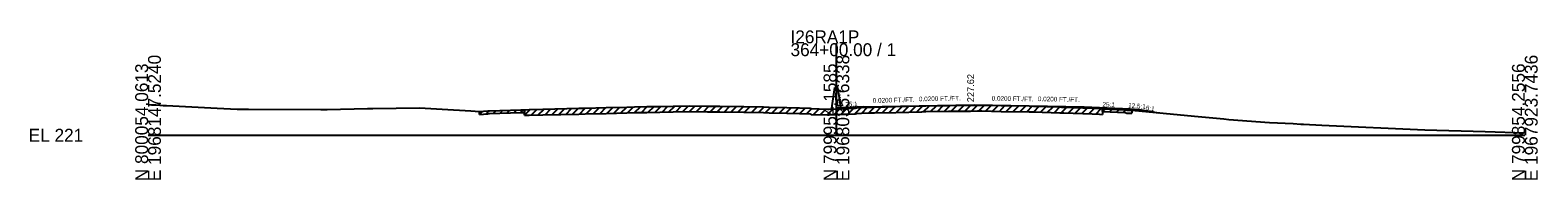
# Model space of a CAD drawing. Extents: x -26 to 304, y -10 to 7527.
# Drawn here: x -25.7 to 302.8, y 6990.3 to 7022.8 of the extents above; entities that cross this region are included whole.
import ezdxf

# ---------------------------------------------------------------- set-up
doc = ezdxf.new("R2010")
doc.units = 0
for name, color, linetype in [('RD_GPK_XS_Cell', 7, 'Continuous'), ('RD_XS_Base', 7, 'Continuous'), ('RD_XS_Box', 7, 'Continuous'), ('RD_XS_EarthShd', 7, 'Continuous'), ('RD_XS_ExGround', 7, 'Continuous'), ('RD_XS_ExPaveRet', 7, 'Continuous'), ('RD_XS_Misc_Line', 7, 'Continuous'), ('RD_XS_Pave', 7, 'Continuous'), ('RD_XS_PaveShd', 7, 'Continuous'), ('RD_XS_TX_Elev_EX', 7, 'Continuous'), ('RD_XS_TX_Elev_PR', 7, 'Continuous'), ('RD_XS_TX_Misc', 7, 'Continuous'), ('RD_XS_TX_MkPT', 7, 'Continuous'), ('RD_XS_TX_Profile', 7, 'Continuous'), ('RD_XS_TX_Station', 7, 'Continuous')]:
    doc.layers.add(name, color=color, linetype=linetype)

msp = doc.modelspace()

# ---------------------------------------------------------------- linework, layer by layer
at = {"layer": 'RD_GPK_XS_Cell'}
for p, q in [((150, 7000), (150, 7020)), ((0, 7000), (150, 7000)), ((150, 7000), (300, 7000))]:
    msp.add_line(p, q, dxfattribs=at)
at = {"layer": 'RD_XS_Base'}
for p, q in [((150, 7005.75), (150, 7005.9)), ((214, 7005.42), (214, 7005.74))]:
    msp.add_line(p, q, dxfattribs=at)
at = {"layer": 'RD_XS_Box'}
msp.add_line((216, 7005.58), (220.21, 7004.88), dxfattribs=at)
at = {"layer": 'RD_XS_EarthShd'}
for p, q in [((149, 7005.92), (149.67, 7010.4)), ((150, 7010.4), (149.67, 7010.4)), ((150, 7010.4), (150.33, 7010.4)), ((151, 7005.92), (150.33, 7010.4)), ((214, 7005.74), (216, 7005.58))]:
    msp.add_line(p, q, dxfattribs=at)
at = {"layer": 'RD_XS_ExGround'}
msp.add_lwpolyline([(0, 7006.67), (0.75, 7006.63), (1.7, 7006.58), (2.53, 7006.54), (3.28, 7006.49), (4.01, 7006.45), (15.09, 7005.87), (19.41, 7005.7), (21.91, 7005.67), (37.63, 7005.59), (39, 7005.57), (47.84, 7005.81), (48.6, 7005.82), (49.01, 7005.83), (59.15, 7005.95), (64.09, 7005.68), (70.33, 7005.3), (72.19, 7005.13), (73.1, 7005.2), (74.06, 7005.27), (74.37, 7005.34), (81.26, 7005.55), (83.06, 7005.61), (86, 7005.68), (93.88, 7005.86), (95.27, 7005.89), (99.82, 7006), (104.36, 7006.13), (105.98, 7006.17), (108.66, 7006.22), (111.54, 7006.28), (114.44, 7006.34), (118.09, 7006.41), (121.91, 7006.35), (123.48, 7006.32), (124.6, 7006.31), (129.85, 7006.26), (134.14, 7006.16), (135.35, 7006.13), (139.19, 7006.04), (141.98, 7005.98), (144.26, 7005.87), (144.51, 7005.79), (148.03, 7005.68), (148.4, 7005.67), (150, 7005.75), (151.08, 7005.81), (152.19, 7005.84), (154.16, 7005.89), (154.41, 7005.98), (155.47, 7006.02), (157.37, 7006.09), (158.31, 7006.11), (162.97, 7006.22), (168.6, 7006.37), (168.93, 7006.38), (169.46, 7006.39), (174.39, 7006.46), (179.24, 7006.51), (180.71, 7006.53), (181.65, 7006.52), (185.92, 7006.44), (192, 7006.37), (192.97, 7006.35), (198.68, 7006.14), (199.05, 7006.13), (199.52, 7006.11), (205.76, 7005.9), (207.3, 7005.82), (212.95, 7005.55), (213.31, 7005.43), (214.4, 7005.42), (228.05, 7004.15), (234.4, 7003.54), (235.53, 7003.43), (244.33, 7002.78), (249.51, 7002.52), (251.18, 7002.44), (251.79, 7002.39), (255.78, 7002.21), (278.21, 7001.17), (291.37, 7000.82), (300, 7000.51)], dxfattribs=at)
at = {"layer": 'RD_XS_ExPaveRet'}
for p, q in [((72.19, 7004.51), (72.19, 7005.13)), ((72.19, 7004.51), (73.1, 7004.57)), ((73.1, 7004.57), (74.06, 7004.64)), ((74.06, 7004.64), (74.37, 7004.72)), ((74.37, 7004.72), (81.26, 7004.93)), ((81.26, 7004.93), (82, 7004.95)), ((82, 7004.33), (82, 7005.58)), ((82, 7005.58), (82, 7004.95)), ((82, 7004.33), (83.06, 7004.36)), ((83.06, 7004.36), (86, 7004.43)), ((86, 7004.43), (93.88, 7004.61)), ((93.88, 7004.61), (95.27, 7004.64)), ((95.27, 7004.64), (99.82, 7004.75)), ((99.82, 7004.75), (104.36, 7004.88)), ((104.36, 7004.88), (105.98, 7004.92)), ((105.98, 7004.92), (108.66, 7004.97)), ((108.66, 7004.97), (111.54, 7005.03)), ((111.54, 7005.03), (114.44, 7005.09)), ((114.44, 7005.09), (118.09, 7005.16)), ((118.09, 7005.16), (121.91, 7005.1)), ((121.91, 7005.1), (123.48, 7005.07)), ((123.48, 7005.07), (124.6, 7005.06)), ((124.6, 7005.06), (129.85, 7005.01)), ((129.85, 7005.01), (134.14, 7004.91)), ((134.14, 7004.91), (135.35, 7004.88)), ((135.35, 7004.88), (139.19, 7004.79)), ((139.19, 7004.79), (141.98, 7004.73)), ((141.98, 7004.73), (144.26, 7004.62)), ((144.26, 7004.62), (144.51, 7004.54)), ((144.51, 7004.54), (148.03, 7004.43)), ((148.03, 7004.43), (148.4, 7004.42)), ((148.4, 7004.42), (150, 7004.5)), ((150, 7004.5), (151.08, 7004.56)), ((151.08, 7004.56), (152.19, 7004.59)), ((152.19, 7004.59), (154.16, 7004.64)), ((154.16, 7004.64), (154.41, 7004.73)), ((154.41, 7004.73), (155.47, 7004.77)), ((155.47, 7004.77), (157.37, 7004.84)), ((157.37, 7004.84), (158.31, 7004.86)), ((158.31, 7004.86), (162.97, 7004.97)), ((162.97, 7004.97), (168.6, 7005.12)), ((168.6, 7005.12), (168.93, 7005.13)), ((168.93, 7005.13), (169.46, 7005.14)), ((169.46, 7005.14), (174.39, 7005.21)), ((174.39, 7005.21), (179.24, 7005.26)), ((179.24, 7005.26), (180.71, 7005.28)), ((180.71, 7005.28), (181.65, 7005.27)), ((181.65, 7005.27), (185.92, 7005.19)), ((185.92, 7005.19), (192, 7005.12)), ((192, 7005.12), (192.97, 7005.1)), ((192.97, 7005.1), (198.68, 7004.89)), ((198.68, 7004.89), (199.05, 7004.88)), ((199.05, 7004.88), (199.52, 7004.86)), ((199.52, 7004.86), (205.76, 7004.65)), ((205.76, 7004.65), (207.3, 7004.57)), ((207.3, 7004.57), (208, 7004.54)), ((208, 7005.79), (208, 7004.54)), ((208, 7005.16), (208, 7005.79)), ((208, 7005.16), (212.95, 7004.93)), ((212.95, 7004.93), (213.31, 7004.81)), ((213.31, 7004.81), (214.4, 7004.79)), ((214.4, 7005.42), (214.4, 7004.79))]:
    msp.add_line(p, q, dxfattribs=at)
at = {"layer": 'RD_XS_Misc_Line'}
for p, q in [((72.19, 7004.51), (72.86, 7005.18)), ((73.69, 7004.62), (74.42, 7005.35)), ((75.19, 7004.74), (75.84, 7005.39)), ((76.69, 7004.79), (77.34, 7005.43)), ((78.19, 7004.83), (78.84, 7005.48)), ((79.69, 7004.88), (80.34, 7005.52)), ((81.19, 7004.93), (81.84, 7005.57)), ((82, 7004.33), (83.29, 7005.61)), ((83.5, 7004.37), (84.78, 7005.65)), ((85, 7004.4), (86.28, 7005.68)), ((86.5, 7004.44), (87.78, 7005.72)), ((88, 7004.47), (89.28, 7005.75)), ((89.5, 7004.51), (90.78, 7005.79)), ((91, 7004.54), (92.28, 7005.82)), ((92.5, 7004.58), (93.78, 7005.85)), ((94, 7004.61), (95.28, 7005.89)), ((95.5, 7004.65), (96.78, 7005.93)), ((97, 7004.68), (98.28, 7005.97)), ((98.5, 7004.72), (99.78, 7006)), ((100, 7004.76), (101.29, 7006.04)), ((101.5, 7004.8), (102.79, 7006.08)), ((103, 7004.84), (104.29, 7006.12)), ((104.5, 7004.88), (105.79, 7006.17)), ((106, 7004.92), (107.27, 7006.2)), ((107.5, 7004.95), (108.77, 7006.23)), ((109, 7004.98), (110.28, 7006.26)), ((110.5, 7005.01), (111.78, 7006.29)), ((112, 7005.04), (113.28, 7006.32)), ((113.5, 7005.07), (114.77, 7006.35)), ((115, 7005.1), (116.27, 7006.37)), ((116.5, 7005.13), (117.77, 7006.4)), ((118, 7005.15), (119.23, 7006.39)), ((119.5, 7005.13), (120.73, 7006.37)), ((121, 7005.11), (122.23, 7006.34)), ((122.5, 7005.09), (123.73, 7006.32)), ((124, 7005.06), (125.24, 7006.3)), ((125.5, 7005.05), (126.74, 7006.29)), ((127, 7005.04), (128.24, 7006.27)), ((128.5, 7005.02), (129.74, 7006.26)), ((130, 7005), (131.22, 7006.23)), ((131.5, 7004.97), (132.72, 7006.19)), ((133, 7004.93), (134.22, 7006.15)), ((134.5, 7004.9), (135.72, 7006.12)), ((136, 7004.86), (137.22, 7006.09)), ((137.5, 7004.83), (138.72, 7006.05)), ((139, 7004.79), (140.22, 7006.02)), ((140.5, 7004.76), (141.72, 7005.98)), ((142, 7004.73), (143.19, 7005.92)), ((143.5, 7004.65), (144.63, 7005.79)), ((145, 7004.52), (146.21, 7005.74)), ((146.5, 7004.48), (147.71, 7005.69)), ((148, 7004.43), (149.28, 7005.72)), ((149.5, 7004.48), (150.82, 7005.79)), ((151, 7004.55), (152.29, 7005.84)), ((152.5, 7004.6), (153.78, 7005.88)), ((154, 7004.63), (155.38, 7006.02)), ((155.5, 7004.77), (156.8, 7006.07)), ((157, 7004.83), (158.28, 7006.11)), ((158.5, 7004.87), (159.78, 7006.15)), ((160, 7004.9), (161.28, 7006.18)), ((161.5, 7004.94), (162.78, 7006.22)), ((163, 7004.97), (164.29, 7006.26)), ((164.5, 7005.01), (165.79, 7006.3)), ((166, 7005.05), (167.29, 7006.34)), ((167.5, 7005.09), (168.79, 7006.38)), ((169, 7005.13), (170.27, 7006.4)), ((170.5, 7005.15), (171.77, 7006.42)), ((172, 7005.17), (173.27, 7006.44)), ((173.5, 7005.19), (174.77, 7006.46)), ((175, 7005.21), (176.27, 7006.48)), ((176.5, 7005.23), (177.77, 7006.5)), ((178, 7005.25), (179.27, 7006.51)), ((179.5, 7005.27), (180.76, 7006.53)), ((181, 7005.28), (182.23, 7006.51)), ((182.5, 7005.25), (183.73, 7006.48)), ((184, 7005.22), (185.23, 7006.45)), ((185.5, 7005.19), (186.73, 7006.43)), ((187, 7005.17), (188.24, 7006.41)), ((188.5, 7005.16), (189.74, 7006.39)), ((190, 7005.14), (191.24, 7006.37)), ((191.5, 7005.12), (192.74, 7006.36)), ((193, 7005.1), (194.21, 7006.31)), ((194.5, 7005.05), (195.71, 7006.25)), ((196, 7004.99), (197.21, 7006.2)), ((197.5, 7004.94), (198.71, 7006.14)), ((199, 7004.88), (200.21, 7006.09)), ((200.5, 7004.83), (201.71, 7006.04)), ((202, 7004.78), (203.21, 7005.99)), ((203.5, 7004.73), (204.71, 7005.93)), ((205, 7004.67), (206.2, 7005.88)), ((206.5, 7004.61), (207.69, 7005.8)), ((208, 7005.16), (208.6, 7005.76)), ((209.5, 7005.09), (210.1, 7005.69)), ((211, 7005.02), (211.6, 7005.62)), ((212.5, 7004.95), (213.07, 7005.51))]:
    msp.add_line(p, q, dxfattribs=at)
at = {"layer": 'RD_XS_Pave'}
for p, q in [((156, 7006.14), (180, 7006.62)), ((180, 7006.62), (204, 7006.14))]:
    msp.add_line(p, q, dxfattribs=at)
at = {"layer": 'RD_XS_PaveShd'}
for p, q in [((156, 7006.14), (150, 7005.9)), ((204, 7006.14), (214, 7005.74))]:
    msp.add_line(p, q, dxfattribs=at)
at = {"layer": 'RD_XS_TX_Elev_PR'}
for p, q in [((150, 7005.75), (151.08, 7005.81)), ((151.08, 7005.81), (152.19, 7005.84)), ((152.19, 7005.84), (154.16, 7005.89)), ((154.16, 7005.89), (154.41, 7005.98)), ((154.41, 7005.98), (155.47, 7006.02)), ((155.47, 7006.02), (157.37, 7006.09)), ((157.37, 7006.09), (158.31, 7006.11)), ((158.31, 7006.11), (162.97, 7006.22)), ((162.97, 7006.22), (168.6, 7006.37)), ((168.6, 7006.37), (168.93, 7006.38)), ((168.93, 7006.38), (169.46, 7006.39)), ((169.46, 7006.39), (174.39, 7006.46)), ((174.39, 7006.46), (179.24, 7006.51)), ((179.24, 7006.51), (180.71, 7006.53)), ((180.71, 7006.53), (181.65, 7006.52)), ((181.65, 7006.52), (185.92, 7006.44)), ((185.92, 7006.44), (192, 7006.37)), ((192, 7006.37), (192.97, 7006.35)), ((192.97, 7006.35), (198.68, 7006.14)), ((198.68, 7006.14), (199.05, 7006.13)), ((199.05, 7006.13), (199.52, 7006.11)), ((199.52, 7006.11), (205.76, 7005.9)), ((205.76, 7005.9), (207.3, 7005.82)), ((207.3, 7005.82), (208, 7005.79)), ((208, 7005.79), (210.13, 7005.69)), ((210.13, 7005.69), (212.95, 7005.55)), ((212.95, 7005.55), (213.31, 7005.43)), ((213.31, 7005.43), (214, 7005.42))]:
    msp.add_line(p, q, dxfattribs=at)

# ---------------------------------------------------------------- texts
at = {"layer": 'RD_GPK_XS_Cell'}
for s, p in [('I26RA1P', (140, 7020)), ('364+00.00 / 1', (140, 7017.2)), ('EL 221', (-26, 6998.6))]:
    msp.add_text(s, height=2.8, dxfattribs=at).set_placement(p)
for s, p in [('N 800054.0613', (0, 6990)), ('E 1968147.5240', (2.8, 6990)), ('N 799954.1585', (150, 6990)), ('E 1968035.6338', (152.8, 6990)), ('N 799854.2556', (300, 6990)), ('E 1967923.7436', (302.8, 6990))]:
    msp.add_text(s, height=2.8, rotation=90, dxfattribs=at).set_placement(p)
at = {"layer": 'RD_XS_TX_Elev_EX'}
msp.add_text('226.75', height=1, rotation=90, dxfattribs=at).set_placement((151, 7005.75))
at = {"layer": 'RD_XS_TX_Misc'}
msp.add_text('12.5:1', height=1, rotation=355.4261, dxfattribs=at).set_placement((213.54, 7006.02))
at = {"layer": 'RD_XS_TX_MkPT'}
for rotation, p in [(2.2906, (151.94, 7006.22)), (357.7094, (207.96, 7006.23))]:
    msp.add_text('25:1', height=1, rotation=rotation, dxfattribs=at).set_placement(p)
at = {"layer": 'RD_XS_TX_Profile'}
for s, rotation, p in [('0.0200 FT./FT.', 1.1458, (157.92, 7007.06)), ('0.0200 FT./FT.', 1.1458, (167.98, 7007.38)), ('0.0200 FT./FT.', 358.8542, (183.83, 7007.54)), ('0.0200 FT./FT.', 358.8542, (193.89, 7007.42)), ('6:1', 350.5377, (217.36, 7005.52))]:
    msp.add_text(s, height=1, rotation=rotation, dxfattribs=at).set_placement(p)
at = {"layer": 'RD_XS_TX_Station'}
msp.add_text(' 227.62', height=1.5, rotation=90, dxfattribs=at).set_placement((180, 7006.62))

doc.saveas('drawing.dxf')
